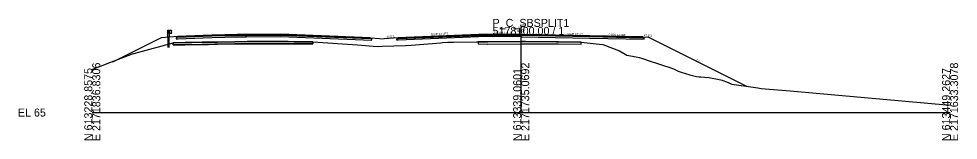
# Model space of a CAD drawing. Extents: x -26 to 1303, y -3010 to 12023.
# Drawn here: x -25.7 to 302.8, y 3490.3 to 3532.8 of the extents above; entities that cross this region are included whole.
import ezdxf

# ---------------------------------------------------------------- set-up
doc = ezdxf.new("R2010")
doc.units = 0
for name, color, linetype in [('RD_GPK_XS_Cell', 7, 'Continuous'), ('RD_PD_Final_TrvlWay', 7, 'Continuous'), ('RD_XS_Base', 7, 'Continuous'), ('RD_XS_ExGround', 7, 'Continuous'), ('RD_XS_ExPaveRet', 7, 'Continuous'), ('RD_XS_GR', 7, 'Continuous'), ('RD_XS_Greenside', 7, 'Continuous'), ('RD_XS_Pave', 7, 'Continuous'), ('RD_XS_PaveOvlay_CP', 7, 'Continuous'), ('RD_XS_TieSlope', 7, 'Continuous'), ('RD_XS_TX_Elev_EX', 7, 'Continuous'), ('RD_XS_TX_Elev_PR', 7, 'Continuous'), ('RD_XS_TX_ShdSlope', 7, 'Continuous'), ('RD_XS_TX_Slope', 7, 'Continuous')]:
    doc.layers.add(name, color=color, linetype=linetype)

msp = doc.modelspace()

# ---------------------------------------------------------------- linework, layer by layer
at = {"layer": 'RD_GPK_XS_Cell'}
for p, q in [((150, 3500), (150, 3530)), ((0, 3500), (150, 3500)), ((150, 3500), (300, 3500))]:
    msp.add_line(p, q, dxfattribs=at)
at = {"layer": 'RD_PD_Final_TrvlWay'}
for p, q in [((26.94, 3526.43), (26.44, 3526.39)), ((26.44, 3526.39), (26.44, 3522.82)), ((26.94, 3522.82), (26.94, 3526.43))]:
    msp.add_line(p, q, dxfattribs=at)
at = {"layer": 'RD_XS_Base'}
for p, q in [((29.75, 3526.34), (29.38, 3526.32)), ((29.38, 3526.32), (29.38, 3526.19)), ((29.38, 3526.19), (29.38, 3525.82)), ((29.38, 3525.82), (29.75, 3525.84)), ((29.88, 3526.34), (29.75, 3526.34)), ((29.75, 3525.84), (29.88, 3525.84)), ((38.75, 3526.7), (29.88, 3526.34)), ((29.88, 3525.84), (38.75, 3526.2)), ((41.88, 3526.82), (38.75, 3526.7)), ((38.75, 3526.2), (41.88, 3526.32)), ((50.75, 3527), (41.88, 3526.82)), ((41.88, 3526.32), (50.75, 3526.5)), ((53.88, 3527.06), (50.75, 3527)), ((50.75, 3526.5), (53.88, 3526.56)), ((53.88, 3527.18), (53.88, 3527.22)), ((53.88, 3527.22), (53.88, 3527.05)), ((53.88, 3527.06), (53.88, 3527.22)), ((53.88, 3527.22), (53.88, 3526.56)), ((53.88, 3527.06), (53.88, 3527.18)), ((65.88, 3527.13), (53.88, 3527.06)), ((53.88, 3526.93), (53.88, 3527.06)), ((53.88, 3527.06), (53.88, 3527.06)), ((53.88, 3527.06), (53.88, 3527.06)), ((53.88, 3527.06), (53.88, 3526.56)), ((53.88, 3527.05), (53.88, 3526.56)), ((53.88, 3526.56), (53.88, 3526.93)), ((53.88, 3526.56), (65.88, 3526.63)), ((53.88, 3526.56), (53.88, 3526.56)), ((53.88, 3526.56), (53.88, 3526.56)), ((53.88, 3526.56), (53.88, 3526.56)), ((97.29, 3525.88), (65.88, 3527.13)), ((65.88, 3526.63), (97.79, 3525.36)), ((97.79, 3525.86), (97.29, 3525.88)), ((97.29, 3525.88), (97.29, 3525.88)), ((97.79, 3525.36), (97.79, 3525.86)), ((97.79, 3525.86), (97.79, 3525.86)), ((97.79, 3525.36), (97.79, 3525.36)), ((97.79, 3525.36), (97.79, 3525.36)), ((106.48, 3525.86), (106.98, 3525.88)), ((106.48, 3525.36), (106.48, 3525.86)), ((106.48, 3525.86), (106.48, 3525.86)), ((106.98, 3525.38), (106.48, 3525.36)), ((106.48, 3525.36), (106.48, 3525.36)), ((106.48, 3525.36), (106.48, 3525.36)), ((106.98, 3525.88), (138, 3527.12)), ((138, 3526.62), (106.98, 3525.38)), ((106.98, 3525.88), (106.98, 3525.88)), ((106.98, 3525.38), (106.98, 3525.38)), ((126, 3526.69), (126, 3526.69)), ((138, 3527.12), (150, 3527.06)), ((150, 3526.56), (138, 3526.62)), ((150, 3527.06), (150, 3527.22)), ((150, 3527.22), (150, 3527.22)), ((150, 3527.22), (150, 3527.22)), ((150, 3527.22), (150, 3526.56)), ((150, 3527.06), (150, 3527.06)), ((162, 3526.82), (150, 3527.06)), ((150, 3527.06), (150, 3527.06)), ((150, 3527.06), (150, 3526.56)), ((150, 3526.56), (150, 3526.56)), ((150, 3526.56), (162, 3526.32)), ((174, 3526.58), (162, 3526.82)), ((162, 3526.82), (162, 3526.82)), ((162, 3526.32), (162, 3526.32)), ((162, 3526.32), (174, 3526.08)), ((192.51, 3526.21), (174, 3526.58)), ((174, 3526.58), (174, 3526.58)), ((174, 3526.08), (174, 3526.08)), ((174, 3526.08), (193.01, 3525.7)), ((193.01, 3526.2), (192.51, 3526.21)), ((192.51, 3526.21), (192.51, 3526.21)), ((193.01, 3525.7), (193.01, 3526.2)), ((193.01, 3526.2), (193.01, 3526.2))]:
    msp.add_line(p, q, dxfattribs=at)
at = {"layer": 'RD_XS_ExGround'}
msp.add_lwpolyline([(0, 3515.07), (2.74, 3516.27), (3.18, 3516.31), (4.01, 3516.73), (6.18, 3517.54), (14.13, 3520.54), (16.25, 3521.15), (28.24, 3524.43), (41.42, 3524.63), (42.5, 3524.64), (42.96, 3524.65), (54.24, 3524.84), (66.33, 3524.85), (66.48, 3524.85), (70.89, 3524.8), (71.01, 3524.8), (71.51, 3524.81), (77.12, 3524.82), (92.72, 3523.68), (99.67, 3523.18), (101.4, 3523.22), (109.49, 3523.5), (111.51, 3523.57), (121.86, 3524.44), (122.51, 3524.5), (124.28, 3524.59), (126.39, 3524.68), (134.37, 3524.79), (134.94, 3524.8), (138.22, 3524.74), (138.36, 3524.73), (150.24, 3524.85), (150.73, 3524.85), (151.46, 3524.85), (162.29, 3524.77), (163.06, 3524.76), (171.02, 3524.69), (176.17, 3524.03), (178.59, 3523.81), (184.35, 3521.65), (186.97, 3520.15), (190.21, 3519.53), (191.28, 3519.25), (192.12, 3519.1), (195.76, 3517.8), (196.68, 3517.47), (199.03, 3516.72), (202.32, 3515.67), (203.31, 3515.29), (204.92, 3514.46), (205.99, 3514.15), (208.96, 3513.24), (211.29, 3512.64), (212.2, 3512.51), (212.85, 3512.55), (215.62, 3512.28), (219.84, 3511.41), (220.25, 3511.35), (220.52, 3511.2), (221.78, 3510.77), (223.63, 3509.9), (232.78, 3508.67), (233.94, 3508.47), (244.1, 3507.57), (300, 3502.56)], dxfattribs=at)
at = {"layer": 'RD_XS_ExPaveRet'}
for points in [[(77.12, 3524.82), (77.12, 3524.48), (77.12, 3524.07), (77.12, 3524.07), (75.96, 3524.07), (73.26, 3524.06), (71.71, 3524.04), (70.99, 3524.05), (70.61, 3524.05), (68.5, 3524.08), (66.78, 3524.1), (65.85, 3524.1), (59.97, 3524.09), (55.28, 3524.09), (54.22, 3524.09), (49.84, 3524.02), (43.79, 3523.91), (42.81, 3523.9), (40.71, 3523.85), (38.44, 3523.84), (32.48, 3523.75), (28.24, 3523.68), (28.24, 3523.68), (28.24, 3523.68), (28.24, 3524.09), (28.24, 3524.43), (28.24, 3524.43), (28.24, 3524.43), (32.48, 3524.5), (38.44, 3524.59), (40.71, 3524.6), (42.81, 3524.65), (43.79, 3524.66), (49.84, 3524.77), (54.22, 3524.84), (55.28, 3524.84), (59.97, 3524.84), (65.85, 3524.85), (66.78, 3524.85), (68.5, 3524.83), (70.61, 3524.8), (70.99, 3524.8), (71.71, 3524.79), (73.26, 3524.81), (75.96, 3524.82), (77.12, 3524.82), (77.12, 3524.82)], [(75.96, 3524.82), (73.26, 3524.81), (71.71, 3524.79), (70.99, 3524.8), (70.61, 3524.8), (68.5, 3524.83), (66.78, 3524.85), (65.85, 3524.85), (59.97, 3524.84), (55.28, 3524.84), (54.22, 3524.84), (49.84, 3524.77), (43.79, 3524.66), (42.81, 3524.65), (40.71, 3524.6), (38.44, 3524.59), (32.48, 3524.5), (28.24, 3524.43), (28.24, 3524.09), (28.24, 3523.68), (32.48, 3523.75), (38.44, 3523.84), (40.71, 3523.85), (42.81, 3523.9), (43.79, 3523.91), (49.84, 3524.02), (54.22, 3524.09), (55.28, 3524.09), (59.97, 3524.09), (65.85, 3524.1), (66.78, 3524.1), (68.5, 3524.08), (70.61, 3524.05), (70.99, 3524.05), (71.71, 3524.04), (73.26, 3524.06), (75.96, 3524.07), (77.12, 3524.07), (77.12, 3524.48), (77.12, 3524.82), (75.96, 3524.82)], [(163.06, 3524.76), (162.29, 3524.77), (162.29, 3524.77), (151.46, 3524.85), (151.46, 3524.85), (150.73, 3524.85), (150.73, 3524.85), (150.73, 3524.85), (150.24, 3524.85), (150.24, 3524.85), (138.36, 3524.73), (138.36, 3524.73), (138.22, 3524.74), (138.22, 3524.74), (134.94, 3524.8), (134.94, 3524.05), (134.94, 3524.05), (138.22, 3523.99), (138.22, 3523.99), (138.36, 3523.98), (138.36, 3523.98), (150.24, 3524.1), (150.24, 3524.1), (150.73, 3524.1), (150.73, 3524.1), (150.73, 3524.1), (151.46, 3524.1), (151.46, 3524.1), (162.29, 3524.02), (162.29, 3524.02), (163.06, 3524.01), (163.06, 3524.01), (171.02, 3523.94), (171.02, 3524.69), (171.02, 3524.69), (163.06, 3524.76), (163.06, 3524.76)], [(163.06, 3524.76), (162.29, 3524.77), (151.46, 3524.85), (150.73, 3524.85), (150.24, 3524.85), (138.36, 3524.73), (138.22, 3524.74), (134.94, 3524.8), (134.94, 3524.05), (138.22, 3523.99), (138.36, 3523.98), (150.24, 3524.1), (150.73, 3524.1), (151.46, 3524.1), (162.29, 3524.02), (163.06, 3524.01), (171.02, 3523.94), (171.02, 3524.69), (163.06, 3524.76)]]:
    msp.add_lwpolyline(points, dxfattribs=at)
at = {"layer": 'RD_XS_GR'}
for p, q in [((26.44, 3526.39), (26.44, 3528.82)), ((26.44, 3528.82), (26.69, 3528.82)), ((26.69, 3528.82), (26.94, 3528.82)), ((26.94, 3528.82), (26.94, 3526.43)), ((26.94, 3527.66), (26.94, 3528.82)), ((26.94, 3528.82), (27.61, 3528.82)), ((27.61, 3528.82), (27.61, 3527.66)), ((27.68, 3528.75), (27.61, 3528.82)), ((27.61, 3528.82), (27.61, 3528.52)), ((27.61, 3528.52), (27.61, 3527.66)), ((27.61, 3528.24), (27.81, 3528.45)), ((27.88, 3528.53), (27.68, 3528.75)), ((27.81, 3528.45), (27.88, 3528.53)), ((26.94, 3526.43), (26.44, 3526.39)), ((27.61, 3527.66), (26.94, 3527.66)), ((27.68, 3528.16), (27.61, 3528.24)), ((27.61, 3527.66), (27.81, 3527.87)), ((27.88, 3527.95), (27.68, 3528.16)), ((27.81, 3527.87), (27.88, 3527.95))]:
    msp.add_line(p, q, dxfattribs=at)
at = {"layer": 'RD_XS_Greenside'}
for p, q in [((24.13, 3526.2), (7.13, 3517.7)), ((194.51, 3526.37), (228.85, 3509.2))]:
    msp.add_line(p, q, dxfattribs=at)
at = {"layer": 'RD_XS_Pave'}
for p, q in [((38.75, 3527.02), (29.88, 3526.66)), ((38.75, 3526.86), (29.88, 3526.5)), ((29.88, 3526.5), (38.75, 3526.86)), ((29.88, 3526.34), (38.75, 3526.7)), ((29.88, 3526.66), (29.88, 3526.62)), ((29.88, 3526.62), (29.88, 3526.5)), ((29.88, 3526.5), (29.88, 3526.46)), ((29.88, 3526.46), (29.88, 3526.34)), ((41.88, 3527.14), (38.75, 3527.02)), ((41.88, 3526.98), (38.75, 3526.86)), ((38.75, 3526.86), (41.88, 3526.98)), ((38.75, 3526.7), (41.88, 3526.82)), ((50.75, 3527.32), (41.88, 3527.14)), ((50.75, 3527.16), (41.88, 3526.98)), ((41.88, 3526.98), (50.75, 3527.16)), ((41.88, 3526.82), (50.75, 3527)), ((53.88, 3527.38), (50.75, 3527.32)), ((53.88, 3527.22), (50.75, 3527.16)), ((50.75, 3527.16), (53.88, 3527.22)), ((50.75, 3527), (53.88, 3527.06)), ((65.88, 3527.45), (53.88, 3527.38)), ((53.88, 3527.38), (53.88, 3527.38)), ((65.88, 3527.29), (53.88, 3527.22)), ((53.88, 3527.22), (65.88, 3527.29)), ((53.88, 3527.18), (53.88, 3527.22)), ((53.88, 3527.22), (53.88, 3527.18)), ((53.88, 3527.22), (53.88, 3527.22)), ((53.88, 3527.22), (53.88, 3527.06)), ((53.88, 3527.06), (53.88, 3527.22)), ((53.88, 3527.22), (53.88, 3527.22)), ((53.88, 3527.06), (53.88, 3527.18)), ((53.88, 3527.18), (53.88, 3527.06)), ((53.88, 3527.06), (65.88, 3527.13)), ((53.88, 3527.06), (53.88, 3527.06)), ((53.88, 3527.06), (53.88, 3527.06)), ((53.88, 3527.06), (53.88, 3527.06)), ((97.29, 3526.2), (65.88, 3527.45)), ((97.29, 3526.04), (65.88, 3527.29)), ((65.88, 3527.29), (97.29, 3526.04)), ((65.88, 3527.13), (97.29, 3525.88)), ((97.29, 3526.04), (97.29, 3526.2)), ((97.29, 3526.2), (97.29, 3526.2)), ((97.29, 3525.88), (97.29, 3526.04)), ((97.29, 3526.04), (97.29, 3526.04)), ((97.29, 3526.04), (97.29, 3526.04)), ((97.29, 3526.04), (97.29, 3526.04)), ((97.29, 3525.88), (97.29, 3525.88)), ((97.29, 3525.88), (97.29, 3525.88)), ((138, 3527.44), (106.98, 3526.2)), ((138, 3527.28), (106.98, 3526.04)), ((106.98, 3526.04), (138, 3527.28)), ((106.98, 3525.88), (138, 3527.12)), ((106.98, 3526.2), (106.98, 3526.2)), ((106.98, 3526.2), (106.98, 3526.04)), ((106.98, 3526.04), (106.98, 3526.04)), ((106.98, 3526.04), (106.98, 3525.88)), ((106.98, 3526.04), (106.98, 3526.04)), ((106.98, 3526.04), (106.98, 3526.04)), ((106.98, 3525.88), (106.98, 3525.88)), ((106.98, 3525.88), (106.98, 3525.88)), ((150, 3527.38), (138, 3527.44)), ((150, 3527.22), (138, 3527.28)), ((138, 3527.28), (150, 3527.22)), ((138, 3527.12), (150, 3527.06)), ((162, 3527.14), (150, 3527.38)), ((150, 3527.38), (150, 3527.38)), ((150, 3527.06), (150, 3527.22)), ((150, 3527.22), (150, 3527.22)), ((150, 3527.22), (150, 3527.22)), ((150, 3527.22), (162, 3526.98)), ((162, 3526.98), (150, 3527.22)), ((150, 3527.22), (150, 3527.22)), ((150, 3527.22), (150, 3527.22)), ((150, 3527.22), (150, 3527.06)), ((150, 3527.06), (150, 3527.06)), ((150, 3527.06), (162, 3526.82)), ((174, 3526.9), (162, 3527.14)), ((162, 3527.14), (162, 3527.14)), ((162, 3526.98), (162, 3526.98)), ((162, 3526.98), (174, 3526.74)), ((174, 3526.74), (162, 3526.98)), ((162, 3526.98), (162, 3526.98)), ((162, 3526.82), (162, 3526.82)), ((162, 3526.82), (174, 3526.58)), ((192.51, 3526.53), (174, 3526.9)), ((174, 3526.9), (174, 3526.9)), ((174, 3526.74), (174, 3526.74)), ((174, 3526.74), (192.51, 3526.37)), ((192.51, 3526.37), (174, 3526.74)), ((174, 3526.74), (174, 3526.74)), ((174, 3526.58), (192.51, 3526.21)), ((174, 3526.58), (174, 3526.58)), ((192.51, 3526.37), (192.51, 3526.53)), ((192.51, 3526.53), (192.51, 3526.53)), ((192.51, 3526.21), (192.51, 3526.37)), ((192.51, 3526.37), (192.51, 3526.37))]:
    msp.add_line(p, q, dxfattribs=at)
at = {"layer": 'RD_XS_PaveOvlay_CP'}
for p, q in [((29.88, 3526.66), (41.88, 3527.14)), ((41.88, 3527.14), (53.88, 3527.38)), ((65.88, 3527.45), (53.88, 3527.38)), ((53.88, 3527.38), (53.88, 3527.38)), ((97.29, 3526.2), (65.88, 3527.45)), ((97.29, 3526.2), (97.29, 3526.2)), ((138, 3527.44), (106.98, 3526.2)), ((106.98, 3526.2), (106.98, 3526.2)), ((150, 3527.38), (138, 3527.44)), ((162, 3527.14), (150, 3527.38)), ((150, 3527.38), (150, 3527.38)), ((174, 3526.9), (162, 3527.14)), ((162, 3527.14), (162, 3527.14)), ((192.51, 3526.53), (174, 3526.9)), ((174, 3526.9), (174, 3526.9))]:
    msp.add_line(p, q, dxfattribs=at)
at = {"layer": 'RD_XS_TieSlope'}
for p, q in [((29.88, 3526.66), (24.13, 3526.2)), ((97.29, 3526.2), (102.12, 3525.81)), ((106.98, 3526.2), (102.12, 3525.81)), ((192.51, 3526.53), (194.51, 3526.37))]:
    msp.add_line(p, q, dxfattribs=at)

# ---------------------------------------------------------------- texts
at = {"layer": 'RD_GPK_XS_Cell'}
for s, p in [('P_C_SBSPLIT1', (140, 3530)), ('5178+00.00 / 1', (140, 3527.2)), ('EL 65', (-26, 3498.6))]:
    msp.add_text(s, height=2.8, dxfattribs=at).set_placement(p)
for s, p in [('N 613228.8575', (0, 3490)), ('E 2171836.8306', (2.8, 3490)), ('N 613339.0601', (150, 3490)), ('E 2171735.0692', (152.8, 3490)), ('N 613449.2627', (300, 3490)), ('E 2171633.3078', (302.8, 3490))]:
    msp.add_text(s, height=2.8, rotation=90, dxfattribs=at).set_placement(p)
at = {"layer": 'RD_XS_TX_Elev_EX'}
msp.add_text('89.85', height=0.6, rotation=90, dxfattribs=at).set_placement((149.74, 3528.02))
at = {"layer": 'RD_XS_TX_Elev_PR'}
msp.add_text('92.38', height=1, rotation=90, dxfattribs=at).set_placement((151.17, 3527.68))
at = {"layer": 'RD_XS_TX_ShdSlope'}
for rotation, p in [(4.5739, (102.89, 3526.12)), (355.4261, (192.84, 3526.82))]:
    msp.add_text('12.5:1', height=0.75, rotation=rotation, dxfattribs=at).set_placement(p)
at = {"layer": 'RD_XS_TX_Slope'}
for s, rotation, p in [('0.040 FT./FT.', 2.2906, (118.43, 3527)), ('0.005 FT./FT.', 359.6897, (140.49, 3527.64)), ('0.020 FT./FT.', 358.8542, (165.94, 3527.16)), ('0.020 FT./FT.', 358.8542, (180.59, 3526.86)), ('2:1', 333.4349, (211.01, 3518.18))]:
    msp.add_text(s, height=0.75, rotation=rotation, dxfattribs=at).set_placement(p)

doc.saveas('drawing.dxf')
